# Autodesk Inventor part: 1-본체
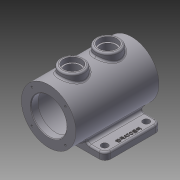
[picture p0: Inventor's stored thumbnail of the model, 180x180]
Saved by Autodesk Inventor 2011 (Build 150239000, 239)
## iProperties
Created: 2014-12
Part Number: 1-본체
Document SubType Name: Modeling
Designer: user
Density: 2.71 g/cm^3
Material: 알루미늄-6061
Mass: 1293.13 g
Surface Area: 1040.18 cm^2
Volume: 477.168 cm^3
Author: user
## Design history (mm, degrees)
sketch "스케치1"
  geometry: L1 (65, -47.5)-(-65, -47.5); L2 (-65, -47.5)-(-65, 47.5); L3 (-65, 47.5)-(65, 47.5); L4 (65, 47.5)-(65, -47.5); L5 (-65, 47.5)-(65, -47.5); 2 further points
  constraints: 10 end point, 2 parallel, 1 coincident, 1 horizontal, 1 midpoint, 1 perpendicular
  dimensions: "d0" = 95 distance of L1.end L2.end; "d1" = 130 distance of L2.end L3.end
extrude "돌출1" new body sketch "스케치1" distance "d2" = 12; taper "d3" = 0 deg
sketch "스케치2"
  geometry: C1 r 46 at (65, 50); 1 further point
  constraints: 1 centre point
  dimensions: "d4" = 92 diameter of C1; "d5" = 50 distance of point (65, 0) C1.centre
extrude "돌출2" join sketch "스케치2" distance "d6" = 30; taper "d8" = 0 deg; dims "d7" = 110, "d9" = 0
sketch "스케치3"
  geometry: C1 r 46 at (0, 0) reference; C2 r 30 at (0, 0); 1 further point
  constraints: 1 centre point, 1 coincident
  dimensions: "d10" = 60 diameter of C2
extrude "돌출3" cut sketch "스케치3" distance "d11" = 800; taper "d12" = 0 deg
node "작업 평면1"
sketch "스케치4"
  geometry: L1 (-65, -50)-(-65, -38) reference; L2 (-65, -38)-(-25.923, -38) reference; L3 (25.923, -38)-(65, -38) reference; L4 (65, -38)-(65, -50) reference; L5 (65, -50)-(-65, -50) reference; C1 r 30 at (0, 0) reference; C2 r 37.5 at (0, 0); A1 r 46 centre (0, 0) between (25.923, -38) and (-25.923, -38) reference; 1 further point
  constraints: 1 centre point, 1 coincident
  dimensions: "d13" = 75 diameter of C2
extrude "돌출4" cut sketch "스케치4" stored distance "d14" = 116; taper "d15" = 0 deg
node "작업 평면2"
sketch "스케치5"
  geometry: C1 r 30 at (0, 0) reference; C2 r 46 at (0, 0) reference; 1 further point
sketch "스케치6"
  geometry: L1 (30, -30)-(-30, -30) reference; L2 (-30, 110)-(30, 110) reference; C1 r 20 at (0, 10); C2 r 20 at (0, 70); 1 further point
  constraints: 2 centre point, 2 vertical alignment
  dimensions: "d16" = 40 diameter of C1; "d17" = 40 distance from line of L1 C1.centre; "d18" = 40 diameter of C2; "d19" = 40 distance from line of L2 C2.centre
extrude "돌출5" join sketch "스케치6" distance "d20" = 10; taper "d22" = 0 deg; dims "d21" = 3, "d23" = 0
sketch "스케치7"
  geometry: C1 r 20 at (0, 0) reference; C2 r 12.5 at (0, 0); 1 further point
  constraints: 1 centre point, 1 coincident
  dimensions: "d24" = 25 diameter of C2
sketch "스케치8"
  geometry: C1 r 20 at (0, 0) reference; C2 r 12.5 at (0, 0); 1 further point
  constraints: 1 centre point, 1 coincident
  dimensions: "d25" = 25 diameter of C2
extrude "돌출6" cut sketch "스케치8" stored distance "d26" = 10; taper "d27" = 0 deg
extrude "돌출7" cut sketch "스케치7" stored distance "d28" = 10; taper "d29" = 0 deg
sketch "스케치9"
  geometry: C1 r 12.5 at (0, 0) reference; C2 r 20 at (0, 0) reference; C3 r 15 at (0, 0); 1 further point
  constraints: 1 centre point, 1 coincident
  dimensions: "d30" = 30 diameter of C3
extrude "돌출8" cut sketch "스케치9" distance "d31" = 8; taper "d32" = 0 deg
sketch "스케치10"
  geometry: C1 r 12.5 at (0, 0) reference; C2 r 20 at (0, 0) reference; C3 r 15 at (0, 0); 1 further point
  constraints: 1 centre point, 1 coincident
  dimensions: "d33" = 30 diameter of C3
extrude "돌출9" cut sketch "스케치10" distance "d34" = 8; taper "d35" = 0 deg
sketch "스케치11"
  geometry: L1 (25.923, 47.5)-(65, 47.5) reference; C1 r 5.5 at (52, 35); 1 further point
  constraints: 1 centre point
  dimensions: "d36" = 52 horizontal distance of C1.centre point (0, 0); "d37" = 12.5 distance from line of L1 C1.centre; "d58" = 11 diameter of C1
extrude "돌출10" cut sketch "스케치11" distance "d38" = 100; taper "d39" = 0 deg
sketch "스케치12" dims "d40" = 80
  geometry: L1 (0, 0)-(81.001, 81.001); L2 (0, 0)-(114.552, 0); C1 r 46 at (0, 0) reference; 2 further points
  constraints: 4 end point, 1 coincident, 1 equal length, 1 horizontal, 1 point on line, 3 other
  dimensions: "d41" = 45 deg angle of L2 L1
hole "Hole1" sketch "스케치12" at (28.284, 28.284) diameter "d42" = 3.242; stored, may be unused: countersink angle "d46" = 90 deg, drill point angle "d48" = 118 deg; dims "d43" = 8, "d44" = 4, "d45" = 2, "d47" = 10
node "작업 평면3"
fillet "모깎기1" dims "d52" = 3
fillet "모깎기2" dims "d53" = 3
chamfer "모따기1" distance "d54" = 1; stored, may be unused: second distance "d55" = 2, angle "d56" = 45 deg
fillet "모깎기3" dims "d57" = 3
fillet "모깎기4" dims "d59" = 10
fillet "모깎기6" dims "d61" = 3
fillet "모깎기7" dims "d62" = 5
fillet "모깎기8" dims "d63" = 3
fillet "모깎기9" dims "d64" = 3
sketch "스케치13"
  geometry: L1 (65, -37.5)-(65, 37.5) reference; C1 r 5.5 at (52, -35) reference; 2 further points
  constraints: 1 other
  dimensions: "d65" = 35 vertical distance of C1.centre point (57, 0); "d66" = 8 distance from line of L1 point (57, 0)
feature "엠보싱1" sketch "스케치13" dims "d67" = 1, "d68" = 0
sketch "스케치14"
  geometry: L1 (-77.5, 19)-(-76.5, 20) reference; L2 (-76.5, 20)-(-65.5, 20) reference; L3 (-65.5, 20)-(-65.5, 15.5) reference; L4 (-62.5, 12.5)-(47.5, 12.5) reference; L5 (50.5, 15.5)-(50.5, 20) reference; L6 (50.5, 20)-(61.5, 20) reference; L7 (61.5, 20)-(62.5, 19) reference; L8 (62.5, 19)-(62.5, 4) reference; L9 (62.5, 4)-(50.5, 4) reference; L10 (47.5, 1)-(47.5, 0) reference; L11 (47.5, 0)-(-47.5, 0) reference; L12 (-47.5, 0)-(-47.5, 1) reference; L13 (-50.5, 4)-(-77.5, 4) reference; L14 (-77.5, 4)-(-77.5, 19) reference; L15 (-54.5, 106)-(-52.5, 106) reference; L16 (-52.5, 106)-(-52.5, 98) reference; L17 (-52.5, 98)-(-50, 98) reference; L18 (-50, 98)-(-50, 87.5) reference; L19 (-50, 87.5)-(-62.5, 87.5) reference; L20 (-65.5, 84.5)-(-65.5, 80) reference; L21 (-65.5, 80)-(-76.5, 80) reference; L22 (-76.5, 80)-(-77.5, 81) reference; L23 (-77.5, 81)-(-77.5, 96) reference; L24 (-77.5, 96)-(-60.5, 96) reference; L25 (-57.5, 99)-(-57.5, 103) reference; L26 (5.5, 106)-(7.5, 106) reference; L27 (7.5, 106)-(7.5, 98) reference; L28 (7.5, 98)-(10, 98) reference; L29 (10, 98)-(10, 87.5) reference; L30 (10, 87.5)-(-25, 87.5) reference; L31 (-25, 87.5)-(-25, 98) reference; L32 (-25, 98)-(-22.5, 98) reference; L33 (-22.5, 98)-(-22.5, 106) reference; L34 (-22.5, 106)-(-20.5, 106) reference; L35 (-17.5, 103)-(-17.5, 99) reference; L36 (-14.5, 96)-(-0.5, 96) reference; L37 (2.5, 99)-(2.5, 103) reference; L38 (42.5, 103)-(42.5, 99) reference; L39 (45.5, 96)-(62.5, 96) reference; L40 (62.5, 96)-(62.5, 81) reference; L41 (62.5, 81)-(61.5, 80) reference; L42 (61.5, 80)-(50.5, 80) reference; L43 (50.5, 80)-(50.5, 84.5) reference; L44 (47.5, 87.5)-(35, 87.5) reference; L45 (35, 87.5)-(35, 98) reference; L46 (35, 98)-(37.5, 98) reference; L47 (37.5, 98)-(37.5, 106) reference; L48 (37.5, 106)-(39.5, 106) reference; A1 r 3 centre (-62.5, 15.5) between (-65.5, 15.5) and (-62.5, 12.5) reference; A2 r 3 centre (47.5, 15.5) between (47.5, 12.5) and (50.5, 15.5) reference; A3 r 3 centre (50.5, 1) between (50.5, 4) and (47.5, 1) reference; A4 r 3 centre (-50.5, 1) between (-47.5, 1) and (-50.5, 4) reference; A5 r 3 centre (-54.5, 103) between (-54.5, 106) and (-57.5, 103) reference; A6 r 3 centre (-62.5, 84.5) between (-62.5, 87.5) and (-65.5, 84.5) reference; A7 r 3 centre (5.5, 103) between (5.5, 106) and (2.5, 103) reference; A8 r 3 centre (-20.5, 103) between (-17.5, 103) and (-20.5, 106) reference; A9 r 3 centre (39.5, 103) between (42.5, 103) and (39.5, 106) reference; A10 r 3 centre (47.5, 84.5) between (50.5, 84.5) and (47.5, 87.5) reference; 1 further point
  constraints: 4 other
  node "절단 모서리 투영2"
node "솔리드1"
mirror "대칭1"
mirror "대칭2"
pattern_circular "원형 패턴1" dims angle "d50" = 360 deg
mirror "대칭3"
node "절단 모서리 투영1"
